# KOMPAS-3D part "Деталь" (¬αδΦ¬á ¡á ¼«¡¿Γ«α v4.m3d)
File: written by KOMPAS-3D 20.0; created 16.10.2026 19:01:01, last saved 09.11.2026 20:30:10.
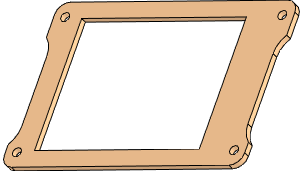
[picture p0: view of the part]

Document properties: Полное имя файла: D:\myProjects\Progect_esp32\box_compas\корпус\крышка на монитор v4.m3d

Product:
- Part/product: Деталь
    Масса: 0.0290543

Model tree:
1. Эскиз:1
2. Элемент выдавливания:1
     Расстояние 1 = 2
3. Элемент выдавливания:2
     Расстояние 1 = 1.5
4. Эскиз:2  (with: Элемент выдавливания:1)
5. Элемент выдавливания:3
     Расстояние 2 = 2
6. Массив по сетке:1  (with: Элемент выдавливания:3, Эскиз:2)  (4 pattern instances)
     Шаг 1 = 75.9; Угол раствора = -90; Шаг 2 = 44.2; Геометрический массив = 128
7. Эскиз:3  (with: Элемент выдавливания:1, Элемент выдавливания:3)
8. Элемент выдавливания:4
     Расстояние 2 = 2
9. Эскиз:4  (with: Элемент выдавливания:1)
10. Элемент выдавливания:5
     Расстояние 2 = 2
11. Смещенная плоскость:2  (with: Элемент выдавливания:1)
     Расстояние = -42
12. Зеркальный массив:1
13. Экземпляр ( 1 )
14. Экземпляр ( 2 )  (with: Элемент выдавливания:5)
15. Скругление:2  (with: Элемент выдавливания:1, Элемент выдавливания:5, Элемент выдавливания:4, Элемент выдавливания:3)
     Радиус = 0.8
16. Скругление:4  (with: Элемент выдавливания:1)
     Радиус = 4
